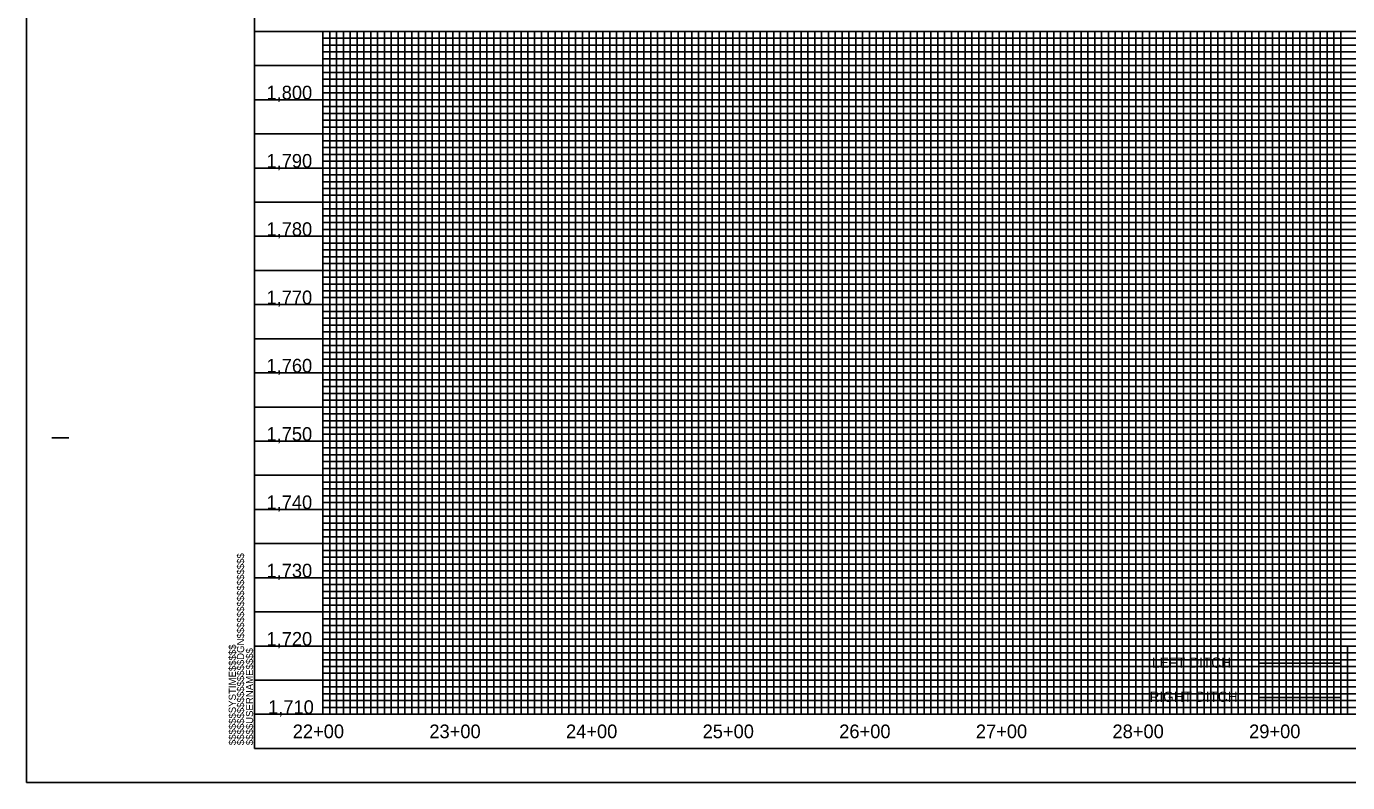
# Model space of a CAD drawing. Extents: x 505602 to 507548, y 483109 to 484209.
# Drawn here: x 505602 to 506569, y 483109 to 483662 of the extents above; entities that cross this region are included whole.
import ezdxf

# ---------------------------------------------------------------- set-up
doc = ezdxf.new("R2010")
doc.units = 0
for name, color, linetype in [('Exist Vertical Profile Vertical Axis Label', 7, 'Continuous'), ('Prop Grid Mask', 7, 'Continuous'), ('Prop PFL Ditch Label CELL', 7, 'Continuous'), ('Prop Vertical Profile Ditch Grade Left', 7, 'Continuous'), ('Sheet Layout Profile Border Port 2', 7, 'Continuous'), ('Sheet Plot Border Outside CELL', 7, 'Continuous'), ('Sheet Profile CELL', 7, 'Continuous'), ('Sheet Profile Grid Major CELL', 7, 'Continuous'), ('Sheet Profile Grid Middle CELL', 7, 'Continuous'), ('Sheet Profile Grid Minor CELL', 7, 'Continuous')]:
    doc.layers.add(name, color=color, linetype=linetype)

msp = doc.modelspace()

# ---------------------------------------------------------------- linework, layer by layer
at = {"layer": 'Prop Grid Mask'}
for points in [[(506419.08, 483208.71), (506569.08, 483208.71), (506569.08, 483183.71), (506419.08, 483183.71)], [(506419.08, 483183.71), (506569.08, 483183.71), (506569.08, 483158.71), (506419.08, 483158.71)]]:
    msp.add_lwpolyline(points, close=True, dxfattribs=at)
at = {"layer": 'Prop PFL Ditch Label CELL'}
for p, q in [((506419.08, 483168.71), (506419.08, 483168.71)), ((506504.63, 483171.06), (506564.63, 483171.06))]:
    msp.add_line(p, q, dxfattribs=at)
at = {"layer": 'Prop Vertical Profile Ditch Grade Left'}
msp.add_line((506504.63, 483196.06), (506564.63, 483196.06), dxfattribs=at)
at = {"layer": 'Sheet Layout Profile Border Port 2'}
msp.add_lwpolyline([(505819.08, 483658.71), (507219.08, 483658.71), (507219.08, 483158.71), (505819.08, 483158.71)], close=True, dxfattribs=at)
msp.add_lwpolyline([(505819.08, 483658.71), (507219.08, 483658.71), (507219.08, 483158.71), (505819.08, 483158.71)], close=True, dxfattribs=at)
at = {"layer": 'Sheet Plot Border Outside CELL'}
msp.add_lwpolyline([(505602.08, 483108.71), (507286.08, 483108.71), (507286.08, 484208.71), (505602.08, 484208.71)], close=True, dxfattribs=at)
at = {"layer": 'Sheet Profile CELL'}
for p, q in [((505769.08, 483658.71), (507269.08, 483658.71)), ((505620.58, 483361.21), (505633.08, 483361.21)), ((507269.08, 483158.71), (505769.08, 483158.71)), ((505769.08, 483133.71), (507269.08, 483133.71)), ((505769.08, 483133.71), (505769.08, 483133.71)), ((505769.08, 483133.71), (505769.08, 483133.71)), ((505769.08, 483133.71), (505769.08, 483133.71)), ((505769.08, 483133.71), (505769.08, 483133.71)), ((505769.08, 483133.71), (505769.08, 483133.71)), ((505769.08, 483133.71), (505769.08, 483133.71)), ((505769.08, 483133.71), (505769.08, 483133.71))]:
    msp.add_line(p, q, dxfattribs=at)
msp.add_lwpolyline([(507269.08, 484183.71), (505769.08, 484183.71), (505769.08, 483133.71), (507269.08, 483133.71)], close=True, dxfattribs=at)
msp.add_lwpolyline([(505806.58, 483133.71), (505806.58, 483133.71)], dxfattribs=at)
at = {"layer": 'Sheet Profile Grid Major CELL'}
for p, q in [((506269.08, 483658.71), (506319.08, 483658.71)), ((506369.08, 483658.71), (506419.08, 483658.71)), ((506469.08, 483658.71), (506519.08, 483658.71))]:
    msp.add_line(p, q, dxfattribs=at)
for points in [[(505819.08, 483658.71), (505819.08, 483158.71), (505869.08, 483158.71), (505869.08, 483658.71), (505919.08, 483658.71), (505919.08, 483158.71), (505969.08, 483158.71), (505969.08, 483658.71), (506019.08, 483658.71), (506019.08, 483158.71), (506069.08, 483158.71), (506069.08, 483658.71), (506119.08, 483658.71), (506119.08, 483158.71), (506169.08, 483158.71), (506169.08, 483658.71), (506219.08, 483658.71), (506219.08, 483158.71), (506269.08, 483158.71), (506269.08, 483658.71), (506319.08, 483658.71), (506319.08, 483158.71), (506369.08, 483158.71), (506369.08, 483658.71), (506419.08, 483658.71), (506419.08, 483158.71), (506469.08, 483158.71), (506469.08, 483658.71), (506519.08, 483658.71), (506519.08, 483158.71), (506569.08, 483158.71)], [(507269.08, 483608.71), (505769.08, 483608.71)], [(507269.08, 483558.71), (505769.08, 483558.71), (505769.08, 483508.71), (507269.08, 483508.71)], [(507269.08, 483458.71), (505769.08, 483458.71), (505769.08, 483408.71), (507269.08, 483408.71)], [(507269.08, 483358.71), (505769.08, 483358.71), (505769.08, 483308.71), (507269.08, 483308.71)], [(507269.08, 483258.71), (505769.08, 483258.71), (505769.08, 483258.71), (505769.08, 483208.71), (507269.08, 483208.71)], [(507269.08, 483158.71), (505769.08, 483158.71)]]:
    msp.add_lwpolyline(points, dxfattribs=at)
at = {"layer": 'Sheet Profile Grid Middle CELL'}
for points in [[(505794.08, 483658.71), (505844.08, 483658.71), (505844.08, 483158.71), (505894.08, 483158.71), (505894.08, 483658.71), (505944.08, 483658.71), (505944.08, 483158.71), (505994.08, 483158.71), (505994.08, 483658.71), (506044.08, 483658.71), (506044.08, 483158.71), (506094.08, 483158.71), (506094.08, 483658.71), (506144.08, 483658.71), (506144.08, 483158.71), (506194.08, 483158.71), (506194.08, 483658.71), (506244.08, 483658.71), (506244.08, 483158.71), (506294.08, 483158.71), (506294.08, 483658.71), (506344.08, 483658.71), (506344.08, 483158.71), (506394.08, 483158.71), (506394.08, 483158.71), (506394.08, 483658.71), (506444.08, 483658.71), (506444.08, 483158.71), (506494.08, 483158.71), (506494.08, 483658.71), (506544.08, 483658.71), (506544.08, 483158.71), (506594.08, 483158.71)], [(505769.08, 483633.71), (507269.08, 483633.71)], [(507269.08, 483583.71), (505769.08, 483583.71), (505769.08, 483533.71), (507269.08, 483533.71)], [(507269.08, 483483.71), (505769.08, 483483.71), (505769.08, 483433.71), (507269.08, 483433.71)], [(507269.08, 483383.71), (505769.08, 483383.71), (505769.08, 483333.71), (507269.08, 483333.71)], [(507269.08, 483283.71), (505769.08, 483283.71), (505769.08, 483233.71), (507269.08, 483233.71)], [(507269.08, 483183.71), (505769.08, 483183.71)]]:
    msp.add_lwpolyline(points, dxfattribs=at)
at = {"layer": 'Sheet Profile Grid Minor CELL'}
for p, q in [((505819.08, 483653.71), (507219.08, 483653.71)), ((507219.08, 483648.71), (505819.08, 483648.71)), ((505819.08, 483643.71), (507219.08, 483643.71)), ((507219.08, 483638.71), (505819.08, 483638.71)), ((505819.08, 483628.71), (507219.08, 483628.71)), ((507219.08, 483623.71), (505819.08, 483623.71)), ((505819.08, 483618.71), (507219.08, 483618.71)), ((507219.08, 483613.71), (505819.08, 483613.71)), ((505819.08, 483603.71), (507219.08, 483603.71)), ((507219.08, 483598.71), (505819.08, 483598.71)), ((505819.08, 483593.71), (507219.08, 483593.71)), ((507219.08, 483588.71), (505819.08, 483588.71)), ((505819.08, 483578.71), (507219.08, 483578.71)), ((507219.08, 483573.71), (505819.08, 483573.71)), ((505819.08, 483568.71), (507219.08, 483568.71)), ((507219.08, 483563.71), (505819.08, 483563.71)), ((505819.08, 483553.71), (507219.08, 483553.71)), ((507219.08, 483548.71), (505819.08, 483548.71)), ((505819.08, 483543.71), (507219.08, 483543.71)), ((507219.08, 483538.71), (505819.08, 483538.71)), ((505819.08, 483528.71), (507219.08, 483528.71)), ((507219.08, 483523.71), (505819.08, 483523.71)), ((505819.08, 483518.71), (507219.08, 483518.71)), ((507219.08, 483513.71), (505819.08, 483513.71)), ((505819.08, 483503.71), (507219.08, 483503.71)), ((507219.08, 483498.71), (505819.08, 483498.71)), ((505819.08, 483493.71), (507219.08, 483493.71)), ((507219.08, 483488.71), (505819.08, 483488.71)), ((505819.08, 483478.71), (507219.08, 483478.71)), ((507219.08, 483473.71), (505819.08, 483473.71)), ((505819.08, 483468.71), (507219.08, 483468.71)), ((507219.08, 483463.71), (505819.08, 483463.86)), ((505819.08, 483453.71), (507219.08, 483453.71)), ((507219.08, 483448.71), (505819.08, 483448.71)), ((505819.08, 483443.71), (507219.08, 483443.71)), ((507219.08, 483438.71), (505819.08, 483438.71)), ((505819.08, 483428.71), (507219.08, 483428.71)), ((507219.08, 483423.71), (505819.08, 483423.71)), ((505819.08, 483418.71), (507219.08, 483418.71)), ((507219.08, 483413.71), (505819.08, 483413.71)), ((505819.08, 483403.71), (507219.08, 483403.71)), ((507219.08, 483398.71), (505819.08, 483398.71)), ((505819.08, 483393.71), (507219.08, 483393.71)), ((507219.08, 483388.71), (505819.08, 483388.71)), ((505819.08, 483378.71), (507219.08, 483378.71)), ((507219.08, 483373.71), (505819.08, 483373.71)), ((505819.08, 483368.71), (507219.08, 483368.71)), ((507219.08, 483363.71), (505819.08, 483363.71)), ((505819.08, 483353.71), (507219.08, 483353.71)), ((507219.08, 483348.71), (505819.08, 483348.71)), ((505819.08, 483343.71), (507219.08, 483343.71)), ((507219.08, 483338.71), (505819.08, 483338.71)), ((505819.08, 483328.71), (507219.08, 483328.71)), ((507219.08, 483323.71), (505819.08, 483323.71)), ((505819.08, 483318.71), (507219.08, 483318.71)), ((507219.08, 483313.71), (505819.08, 483313.71)), ((505819.08, 483303.71), (507219.08, 483303.71)), ((507219.08, 483298.71), (505819.08, 483298.71)), ((505819.08, 483293.71), (507219.08, 483293.71)), ((507219.08, 483288.71), (505819.08, 483288.71)), ((505819.08, 483278.71), (507219.08, 483278.71)), ((507219.08, 483273.71), (505819.08, 483273.71)), ((505819.08, 483268.71), (507219.08, 483268.71)), ((507219.08, 483263.71), (505819.08, 483263.71)), ((505819.08, 483253.71), (507219.08, 483253.71)), ((507219.08, 483248.71), (505819.08, 483248.71)), ((505819.08, 483243.71), (507219.08, 483243.71)), ((507219.08, 483238.71), (505819.08, 483238.71)), ((505819.08, 483228.71), (507219.08, 483228.71)), ((507219.08, 483223.71), (505819.08, 483223.71)), ((505819.08, 483218.71), (507219.08, 483218.71)), ((507219.08, 483213.71), (505819.08, 483213.71)), ((505819.08, 483203.71), (507219.08, 483203.71)), ((507219.08, 483198.71), (505819.08, 483198.71)), ((505819.08, 483193.71), (507219.08, 483193.71)), ((507219.08, 483188.71), (505819.08, 483188.71)), ((505819.08, 483178.71), (507219.08, 483178.71)), ((507219.08, 483173.71), (505819.08, 483173.71)), ((505819.08, 483168.71), (507219.08, 483168.71)), ((505819.08, 483163.71), (507219.08, 483163.71))]:
    msp.add_line(p, q, dxfattribs=at)
for points in [[(505819.08, 483658.71), (505824.08, 483658.71), (505824.08, 483158.71), (505829.08, 483158.71), (505829.08, 483658.71), (505834.08, 483658.71), (505834.08, 483158.71), (505839.08, 483158.71), (505839.08, 483658.71), (505849.08, 483658.71), (505849.08, 483158.71), (505854.08, 483158.71), (505854.08, 483658.71), (505859.08, 483658.71), (505859.08, 483158.71), (505864.08, 483158.71), (505874.08, 483158.71), (505879.08, 483158.71), (505879.08, 483658.71), (505884.08, 483658.71), (505884.08, 483158.71), (505889.08, 483158.71), (505889.08, 483658.71), (505899.08, 483658.71), (505899.08, 483158.71), (505904.08, 483158.71), (505904.08, 483658.71), (505909.08, 483658.71), (505909.08, 483158.71), (505914.08, 483158.71), (505914.08, 483658.71), (505924.08, 483658.71), (505924.08, 483158.71), (505929.08, 483158.71), (505929.08, 483658.71), (505934.08, 483658.71), (505934.08, 483158.71), (505939.08, 483158.71), (505939.08, 483658.71), (505949.08, 483658.71), (505949.08, 483158.71), (505954.08, 483158.71), (505954.08, 483658.71), (505959.08, 483658.71), (505959.08, 483158.71), (505964.08, 483158.71), (505964.08, 483658.71), (505974.08, 483658.71), (505974.08, 483158.71), (505979.08, 483158.71), (505979.08, 483658.71), (505984.08, 483658.71), (505984.08, 483158.71), (505989.08, 483158.71), (505989.08, 483658.71), (505999.08, 483658.71), (505999.08, 483158.71), (506004.08, 483158.71), (506004.08, 483658.71), (506009.08, 483658.71), (506009.08, 483158.71), (506014.08, 483158.71), (506014.08, 483658.71), (506024.08, 483658.71), (506024.08, 483158.71), (506029.08, 483158.71), (506029.08, 483658.71), (506034.08, 483658.71), (506034.08, 483158.71)], [(505864.08, 483158.71), (505864.08, 483658.71), (505874.08, 483658.71), (505874.08, 483158.71)], [(506034.08, 483158.71), (506039.08, 483158.71), (506039.08, 483658.71), (506049.08, 483658.71), (506049.08, 483158.71), (506054.08, 483158.71), (506054.08, 483658.71), (506059.08, 483658.71), (506059.08, 483158.71), (506064.08, 483158.71), (506064.08, 483658.71), (506074.08, 483658.71), (506074.08, 483158.71), (506079.08, 483158.71), (506079.08, 483658.71), (506084.08, 483658.71), (506084.08, 483158.71), (506089.08, 483158.71), (506089.08, 483658.71), (506099.08, 483658.71), (506099.08, 483158.71), (506104.08, 483158.71), (506104.08, 483658.71), (506109.08, 483658.71), (506109.08, 483158.71), (506114.08, 483158.71), (506114.08, 483658.71), (506124.08, 483658.71), (506124.08, 483158.71), (506129.08, 483158.71), (506129.08, 483658.71), (506134.08, 483658.71), (506134.08, 483158.71), (506139.08, 483158.71), (506139.08, 483658.71), (506149.08, 483658.71), (506149.08, 483158.71), (506154.08, 483158.71), (506154.08, 483658.71), (506159.08, 483658.71), (506159.08, 483158.71), (506164.08, 483158.71), (506164.08, 483658.71), (506174.08, 483658.71), (506174.08, 483158.71), (506179.08, 483158.71), (506179.08, 483658.71), (506184.08, 483658.71), (506184.08, 483158.71), (506189.08, 483158.71), (506189.08, 483658.71), (506199.08, 483658.71), (506199.08, 483158.71), (506204.08, 483158.71), (506204.08, 483658.71), (506209.08, 483658.71), (506209.08, 483158.71), (506214.08, 483158.71), (506214.08, 483658.71), (506224.08, 483658.71), (506224.08, 483158.71), (506229.08, 483158.71), (506229.08, 483658.71), (506234.08, 483658.71), (506234.08, 483158.71), (506239.08, 483158.71), (506239.08, 483658.71), (506249.08, 483658.71), (506249.08, 483158.71), (506254.08, 483158.71), (506254.08, 483658.71), (506259.08, 483658.71), (506259.08, 483158.71), (506264.08, 483158.71), (506264.08, 483658.71), (506274.08, 483658.71), (506274.08, 483158.71), (506279.08, 483158.71), (506279.08, 483658.71), (506284.08, 483658.71), (506284.08, 483158.71), (506289.08, 483158.71), (506289.08, 483658.71), (506299.08, 483658.71), (506299.08, 483158.71), (506304.08, 483158.71), (506304.08, 483658.71), (506309.08, 483658.71), (506309.08, 483158.71), (506314.08, 483158.71), (506314.08, 483658.71), (506324.08, 483658.71), (506324.08, 483158.71), (506329.08, 483158.71), (506329.08, 483658.71), (506334.08, 483658.71), (506334.08, 483158.71), (506339.08, 483158.71), (506339.08, 483658.71), (506349.08, 483658.71)], [(506349.08, 483658.71), (506349.08, 483158.71), (506354.08, 483158.71), (506354.08, 483658.71), (506359.08, 483658.71), (506359.08, 483158.71), (506364.08, 483158.71), (506364.08, 483658.71), (506374.08, 483658.71), (506374.08, 483158.71), (506379.08, 483158.71), (506379.08, 483658.71), (506384.08, 483658.71), (506384.08, 483158.71), (506389.08, 483158.71), (506389.08, 483658.71), (506399.08, 483658.71), (506399.08, 483158.71), (506404.08, 483158.71), (506404.08, 483658.71), (506409.08, 483658.71), (506409.08, 483158.71), (506414.08, 483158.71), (506414.08, 483658.71), (506424.08, 483658.71), (506424.08, 483158.71), (506429.08, 483158.71), (506429.08, 483658.71), (506434.08, 483658.71), (506434.08, 483158.71), (506439.08, 483158.71), (506439.08, 483658.71), (506449.08, 483658.71), (506449.08, 483158.71), (506454.08, 483158.71), (506454.08, 483658.71), (506459.08, 483658.71), (506459.08, 483158.71), (506464.08, 483158.71), (506464.08, 483658.71), (506474.08, 483658.71), (506474.08, 483158.71), (506474.08, 483158.71), (506479.08, 483158.71), (506479.08, 483658.71), (506484.08, 483658.71), (506484.08, 483158.71), (506489.08, 483158.71), (506489.08, 483658.71), (506499.08, 483658.71), (506499.08, 483158.71), (506504.08, 483158.71), (506504.08, 483658.71), (506509.08, 483658.71), (506509.08, 483158.71), (506514.08, 483158.71), (506514.08, 483658.71), (506524.08, 483658.71), (506524.08, 483158.71), (506529.08, 483158.71), (506529.08, 483658.71), (506534.08, 483658.71), (506534.08, 483158.71), (506539.08, 483158.71), (506539.08, 483658.71), (506549.08, 483658.71), (506549.08, 483158.71), (506554.08, 483158.71), (506554.08, 483658.71), (506559.08, 483658.71), (506559.08, 483158.71), (506564.08, 483158.71), (506564.08, 483658.71), (506574.08, 483658.71)]]:
    msp.add_lwpolyline(points, dxfattribs=at)

# ---------------------------------------------------------------- texts
at = {"layer": 'Exist Vertical Profile Vertical Axis Label'}
for s, p in [('1,800', (505777.78, 483608.96)), ('1,790', (505777.78, 483558.96)), ('1,780', (505777.78, 483508.96)), ('1,770', (505777.78, 483458.96)), ('1,760', (505777.78, 483408.96)), ('1,750', (505777.78, 483358.96)), ('1,740', (505777.78, 483308.96)), ('1,730', (505777.78, 483258.96)), ('1,720', (505777.78, 483208.96)), ('1,710', (505778.97, 483158.96)), ('22+00', (505797.01, 483141.21)), ('23+00', (505897.01, 483141.21)), ('24+00', (505997.01, 483141.21)), ('25+00', (506097.01, 483141.21)), ('26+00', (506197.01, 483141.21)), ('27+00', (506297.01, 483141.21)), ('28+00', (506397.01, 483141.21)), ('29+00', (506497.01, 483141.21))]:
    msp.add_text(s, height=10, dxfattribs=at).set_placement(p)
at = {"layer": 'Prop PFL Ditch Label CELL'}
msp.add_text('RIGHT DITCH', height=7.485, dxfattribs=at).set_placement((506424.08, 483167.81))
at = {"layer": 'Prop Vertical Profile Ditch Grade Left'}
msp.add_text('LEFT DITCH', height=7.485, dxfattribs=at).set_placement((506425.91, 483192.81))
at = {"layer": 'Sheet Profile CELL'}
for s, p in [('$$$$$$$$$$$$$$$$DGN$$$$$$$$$$$$$$$$', (505761.44, 483136.09)), ('$$$$$$SYSTIME$$$$$', (505755.39, 483136.09)), ('$$$$USERNAME$$$$', (505768.02, 483136.1))]:
    msp.add_text(s, height=5.25, rotation=90, dxfattribs=at).set_placement(p)

doc.saveas('drawing.dxf')
